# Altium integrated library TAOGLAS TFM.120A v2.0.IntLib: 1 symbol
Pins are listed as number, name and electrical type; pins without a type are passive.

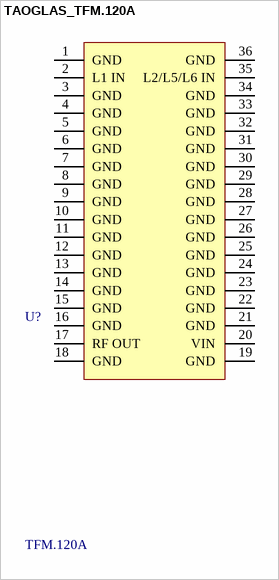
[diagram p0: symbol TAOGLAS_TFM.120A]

## TAOGLAS_TFM.120A
designator U?, comment TFM.120A
Surface mount GNSS front-end module covering L1+B1+G1/L2/L5/L6+L-band; MFG: Taoglas; Temp_High: +85C; Temp_Low: -40C; ComponentLibStatus: Created
footprint TAOGLAS_TFM.120A (Surface mount GNSS front-end module covering L1+B1+G1/L2/L5/L6+L-band)
pins: 1 GND, 2 L1 IN, 3 GND, 4 GND, 5 GND, 6 GND, 7 GND, 8 GND, 9 GND, 10 GND, 11 GND, 12 GND, 13 GND, 14 GND, 15 GND, 16 GND, 17 RF OUT, 18 GND, 19 GND, 20 VIN, 21 GND, 22 GND, 23 GND, 24 GND, 25 GND, 26 GND, 27 GND, 28 GND, 29 GND, 30 GND, 31 GND, 32 GND, 33 GND, 34 GND, 35 L2/L5/L6 IN, 36 GND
